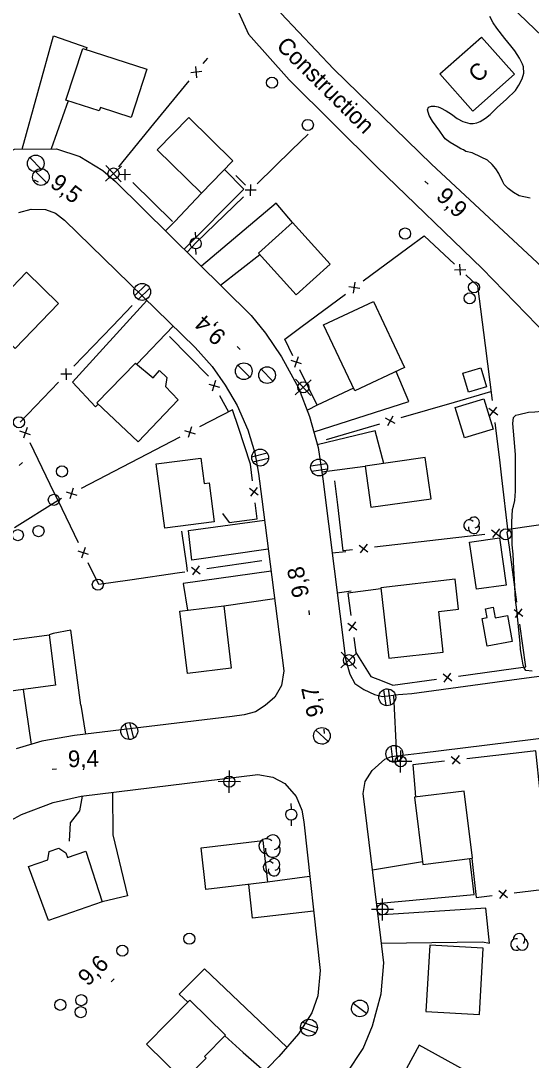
# Model space of a CAD drawing. Extents: x 381879 to 384696, y 5564785 to 5567594.
# Drawn here: x 383271.9 to 383363.8, y 5565601.7 to 5565788.8 of the extents above; entities that cross this region are included whole.
import ezdxf

# ---------------------------------------------------------------- set-up
doc = ezdxf.new("R2010")
doc.units = 0
for name, color, linetype in [('Niveau 1', 7, 'Continuous'), ('Niveau 19', 7, 'Continuous'), ('Niveau 21', 7, 'Continuous'), ('Niveau 3', 7, 'Continuous'), ('Niveau 31', 7, 'Continuous'), ('Niveau 36', 7, 'Continuous'), ('Niveau 37', 7, 'Continuous'), ('Niveau 41', 7, 'Continuous'), ('Niveau 44', 7, 'Continuous')]:
    doc.layers.add(name, color=color, linetype=linetype)

msp = doc.modelspace()

# ---------------------------------------------------------------- linework, layer by layer
at = {"layer": 'Niveau 1'}
for points in [[(383363.59, 5565756.86), (383361.64, 5565757.29), (383360.57, 5565757.89), (383359.63, 5565758.59), (383358.9, 5565759.33), (383358.68, 5565759.83), (383357.94, 5565761.3), (383357.43, 5565762.17), (383356.76, 5565762.92), (383355.91, 5565763.69), (383354.79, 5565764.27), (383353.13, 5565765.02), (383352.04, 5565765.29), (383351.6, 5565765.57), (383351.11, 5565765.74), (383350.61, 5565766.08), (383349.17, 5565766.92), (383348.32, 5565767.54), (383347.97, 5565767.98), (383347.33, 5565768.92), (383345.99, 5565770.73), (383345.42, 5565771.78), (383345.12, 5565772.78), (383345.29, 5565773.27), (383345.84, 5565773.45), (383346.44, 5565773.46), (383347.02, 5565773.34), (383347.48, 5565773.14), (383348.47, 5565772.62), (383349.44, 5565772), (383350.43, 5565771.23), (383351.48, 5565770.67), (383352.71, 5565770.32), (383353.33, 5565770.31), (383353.98, 5565770.42), (383354.6, 5565770.65), (383355.55, 5565771.25), (383356.37, 5565771.95), (383357.66, 5565773.18), (383359.32, 5565774.68), (383360.94, 5565776.25), (383361.58, 5565777.2), (383362.16, 5565778.35), (383362.45, 5565779.39), (383362.4, 5565780.51), (383362.23, 5565781.02), (383361.69, 5565782.05), (383360.82, 5565783.42), (383360.13, 5565784.32), (383359.05, 5565785.6), (383357.6, 5565787.47), (383356.95, 5565788.43), (383356.35, 5565789.59)], [(383360.98, 5565710.72), (383360.74, 5565713.52), (383360.45, 5565716.3), (383360.62, 5565717.41), (383361.01, 5565717.8), (383361.54, 5565717.94), (383363.32, 5565718.34), (383364.45, 5565718.4), (383365.68, 5565718.55), (383367.56, 5565718.87), (383369.37, 5565719.13), (383370.52, 5565719.14), (383371.63, 5565719.23), (383372.71, 5565719.42), (383373.81, 5565719.45), (383374.9, 5565719.24), (383375.95, 5565718.62)], [(383363.96, 5565671.74), (383362.85, 5565671.86), (383362.54, 5565672.29), (383362.36, 5565672.78), (383362.14, 5565673.9), (383361.87, 5565675.61), (383361.77, 5565676.74), (383361.51, 5565679.72), (383361.2, 5565682.76), (383360.96, 5565684.58), (383360.91, 5565685.64), (383360.8, 5565688.25), (383360.67, 5565690.17), (383360.53, 5565692.75), (383360.35, 5565694.43), (383360.34, 5565695.62), (383360.29, 5565698.52), (383360.43, 5565700.79), (383360.61, 5565701.4), (383360.81, 5565702.47), (383360.96, 5565704.14), (383360.96, 5565705.33), (383360.93, 5565708.19), (383360.95, 5565710.53), (383360.98, 5565710.72)]]:
    msp.add_lwpolyline(points, dxfattribs=at)
at = {"layer": 'Niveau 19'}
for points in [[(383272.12, 5565765.72), (383277.78, 5565786.1), (383283.8, 5565784.02), (383283.66, 5565783.63)], [(383280.42, 5565774.41), (383277.38, 5565765.74)], [(383308.55, 5565762.03), (383312.03, 5565758.51), (383301.29, 5565747.68)], [(383299.62, 5565752.66), (383304.4, 5565757.79)], [(383320.83, 5565752.49), (383317.89, 5565756), (383304.4, 5565744.61)], [(383299.62, 5565752.66), (383297.97, 5565750.96)], [(383303.47, 5565748.88), (383301.84, 5565747.14)], [(383307.82, 5565741.23), (383314.95, 5565746.7)], [(383285.83, 5565719.79), (383285.37, 5565719.31), (383281.18, 5565723.75), (383294.59, 5565738.42), (383294.61, 5565738.44)], [(383299.35, 5565733.82), (383292.76, 5565726.98)], [(383324.64, 5565714.79), (383324.73, 5565714.82), (383341.76, 5565720.29), (383339.49, 5565725.68)], [(383325.26, 5565719.63), (383323.5, 5565718.72), (383323.45, 5565718.7)], [(383337.24, 5565709.1), (383335.7, 5565715.01), (383325.27, 5565712.48)], [(383326.08, 5565707.59), (383333.87, 5565708.62)], [(383316.44, 5565693.68), (383302.69, 5565691.7), (383302.09, 5565697.02), (383315.77, 5565698.91)], [(383327.95, 5565692.99), (383330.44, 5565693.28)], [(383316.95, 5565689.71), (383301.14, 5565687.51), (383301.91, 5565682.67)], [(383331.36, 5565686.11), (383328.86, 5565685.75)], [(383308.43, 5565683.46), (383317.58, 5565684.81)], [(383282.73, 5565665.6), (383280.91, 5565679.09), (383277.7, 5565678.51), (383276.98, 5565678.23)], [(383272.34, 5565668.42), (383273.76, 5565658.54)], [(383282.73, 5565665.6), (383283.56, 5565660.37)], [(383280.65, 5565641.09), (383280.87, 5565644.42), (383282.53, 5565646.57), (383283.01, 5565649.21)], [(383288.42, 5565649.88), (383288.42, 5565649.8), (383288.44, 5565642.24), (383291.11, 5565631.26), (383286.54, 5565630.17)], [(383344.19, 5565637.4), (383335.21, 5565635.87)], [(383335.94, 5565629.86), (383353.51, 5565631.5), (383352.75, 5565637.96)], [(383323.92, 5565634.74), (383323.89, 5565634.74), (383316.32, 5565633.71)], [(383324.62, 5565628.53), (383313.62, 5565627.25), (383312.92, 5565633.32)], [(383355.03, 5565622.96), (383356.26, 5565622.76), (383355.62, 5565629.07), (383336.2, 5565627.78)], [(383336.8, 5565622.77), (383355.03, 5565622.96)], [(383319.81, 5565604), (383304.95, 5565618.1), (383300.38, 5565613.54), (383301.95, 5565612.12)], [(383308.64, 5565606.08), (383311.95, 5565603.09), (383315.79, 5565599.7)]]:
    msp.add_lwpolyline(points, dxfattribs=at)
at = {"layer": 'Niveau 21'}
for points in [[(383340.03, 5565839.61), (383323.72, 5565821.69), (383314.72, 5565812.08), (383308.82, 5565803.38), (383308.34, 5565796.45), (383312.87, 5565786.42), (383320.23, 5565778.18), (383336.03, 5565762.43), (383354.96, 5565744.23), (383378.72, 5565719.74), (383396.75, 5565701.57), (383402.38, 5565696.34)], [(383410.35, 5565703.77), (383396.72, 5565715.26), (383371.77, 5565738.86), (383345.81, 5565763), (383328.26, 5565780.1), (383318.72, 5565790.17), (383316.51, 5565795.66), (383316.17, 5565800.57), (383317.61, 5565803.6), (383321.37, 5565807.43), (383341.84, 5565826.74), (383347.6, 5565832.19), (383347.6, 5565832.19)], [(383165.2, 5565662.3), (383255.18, 5565754.08), (383259.47, 5565758.71), (383263.74, 5565762.5), (383270.79, 5565765.71), (383278.33, 5565765.75), (383282.52, 5565764.39), (383286.66, 5565761.84), (383288.94, 5565759.87), (383313.36, 5565735.76), (383315.98, 5565732.55), (383318.83, 5565728.32), (383321.91, 5565722.74), (383323.89, 5565717.55), (383325.41, 5565711.97), (383326.27, 5565706.34), (383330.34, 5565673.96), (383331.12, 5565671.16), (383332.04, 5565669.52), (383333.66, 5565668.42), (383335.55, 5565667.51), (383337.01, 5565667.18), (383339.08, 5565667.37)], [(383271.52, 5565754.32), (383273.79, 5565754.89), (383276.33, 5565754.84), (383278.17, 5565754.19), (383279.77, 5565752.88), (383303.28, 5565730), (383306.34, 5565726.55), (383308.7, 5565723.2), (383310.84, 5565719.55), (383312.78, 5565715.14), (383314.01, 5565711.05), (383314.66, 5565707.33), (383315.28, 5565702.69), (383319.26, 5565671.77), (383318.82, 5565669.13), (383317.65, 5565667.02), (383315.91, 5565665.54), (383314.17, 5565664.41), (383312.1, 5565663.86), (383309.96, 5565663.57), (383281.56, 5565660.13), (383275.66, 5565659.09), (383271.05, 5565657.75)], [(383339.61, 5565656.47), (383343.68, 5565656.98), (383388.48, 5565662.48), (383391.99, 5565663.35), (383396.16, 5565665.21), (383399.25, 5565667.19), (383403.25, 5565671.11), (383413, 5565680.41), (383416.17, 5565681.69), (383419.45, 5565680.99), (383421.64, 5565679.31), (383428.7, 5565687.33), (383426.92, 5565690.54), (383426.72, 5565693.02), (383427.78, 5565695.77), (383429.79, 5565697.9), (383459.04, 5565728.3), (383460.02, 5565728.69)], [(383402.38, 5565696.34), (383404.81, 5565693.32), (383405.33, 5565690.79), (383404.5, 5565688.15), (383392.17, 5565675.84), (383389.36, 5565674.25), (383385.14, 5565673.33), (383362.94, 5565670.46), (383342.29, 5565667.66), (383339.08, 5565667.37)], [(383339.61, 5565656.47), (383339.08, 5565667.37)], [(383279.7, 5565546.8), (383330.59, 5565599.35), (383333.54, 5565603.77), (383335.2, 5565607.85), (383336.77, 5565613.62), (383337.23, 5565619.22), (383336.69, 5565623.71), (383333.54, 5565649.66), (383333.88, 5565651.87), (383335.17, 5565653.84), (383337.46, 5565655.87), (383338.63, 5565656.35), (383339.61, 5565656.47)], [(383225.4, 5565600.6), (383260.79, 5565637.22), (383264.27, 5565640.61), (383268.01, 5565643.77), (383272.04, 5565645.91), (383277.7, 5565648.06), (383282.77, 5565649.18), (383314.56, 5565653.12), (383317.26, 5565652.66), (383319.46, 5565651.5), (383321.49, 5565649.13), (383322.5, 5565646.69), (383322.83, 5565644.58), (383325.81, 5565617.8), (383325.38, 5565613.29), (383324.28, 5565610.19), (383321.91, 5565606.43), (383318.36, 5565602.32), (383314.44, 5565598.32), (383271.8, 5565554.6)]]:
    msp.add_lwpolyline(points, dxfattribs=at)
at = {"layer": 'Niveau 3'}
for p, q in [((383274.32, 5565760.2), (383275, 5565759.79)), ((383344.65, 5565759.95), (383345.22, 5565759.38)), ((383311.4, 5565729.62), (383310.85, 5565730.19)), ((383271.61, 5565708.73), (383272.18, 5565709.3)), ((383323.9, 5565681.86), (383323.8, 5565682.65)), ((383326.59, 5565660.5), (383326.49, 5565661.29)), ((383277.54, 5565654.08), (383278.34, 5565654.14)), ((383288.15, 5565615.76), (383288.72, 5565616.33))]:
    msp.add_line(p, q, dxfattribs=at)
at = {"layer": 'Niveau 31'}
for points in [[(383347.36, 5565779.24), (383354.83, 5565785.88), (383360.76, 5565779.2), (383353.29, 5565772.56)], [(383283.07, 5565783.82), (383294.6, 5565780.08), (383291.78, 5565771.38), (383286.22, 5565773.18), (383286.02, 5565772.57), (383280.02, 5565774.54)], [(383302.12, 5565771.39), (383310.08, 5565763.58), (383304.4, 5565757.79), (383296.44, 5565765.6)], [(383320.83, 5565752.49), (383327.59, 5565745.01), (383321.47, 5565739.48), (383314.71, 5565746.96)], [(383278.71, 5565737.92), (383270.88, 5565729.83), (383265.1, 5565735.43), (383272.93, 5565743.52)], [(383335.39, 5565738.27), (383340.99, 5565726.39), (383332.01, 5565722.16), (383326.41, 5565734.04)], [(383300.23, 5565720.58), (383293.01, 5565712.99), (383285.57, 5565720.04), (383292.54, 5565727.17), (383295.72, 5565724.51), (383296.86, 5565725.86), (383298.2, 5565724.6), (383297.93, 5565722.95)], [(383355.71, 5565722.91), (383352.48, 5565721.96), (383351.48, 5565725.36), (383354.71, 5565726.31)], [(383351.76, 5565713.7), (383350.11, 5565719.16), (383355.28, 5565720.72), (383356.93, 5565715.26)], [(383297.8, 5565697.43), (383296.29, 5565709.02), (383304.29, 5565710.06), (383304.88, 5565705.51), (383305.79, 5565705.63), (383306.72, 5565698.61)], [(383344.72, 5565710.18), (383333.87, 5565708.62), (383334.93, 5565701.21), (383345.78, 5565702.76)], [(383358.09, 5565695.73), (383359.3, 5565687.22), (383353.91, 5565686.45), (383352.7, 5565694.96)], [(383336.7, 5565686.74), (383338.14, 5565674.04), (383347.96, 5565675.15), (383347.13, 5565682.46), (383350.7, 5565682.87), (383350.08, 5565688.28)], [(383301.89, 5565671.27), (383300.52, 5565682.5), (383308.43, 5565683.46), (383309.79, 5565672.23)], [(383359.52, 5565681.74), (383360.37, 5565677.04), (383355.86, 5565676.21), (383354.95, 5565681.19), (383355.83, 5565681.35), (383355.54, 5565682.96), (383356.96, 5565683.22), (383357.31, 5565681.33)], [(383265.72, 5565676.75), (383276.98, 5565678.23), (383278.16, 5565669.19), (383266.9, 5565667.71)], [(383353.24, 5565638.02), (383351.74, 5565650.14), (383342.75, 5565649.02), (383344.25, 5565636.9)], [(383316.32, 5565633.71), (383305.2, 5565632.43), (383304.34, 5565639.92), (383315.46, 5565641.2)], [(383286.54, 5565630.17), (383276.89, 5565626.82), (383273.31, 5565636.57), (383276.74, 5565637.73), (383277.02, 5565639.24), (383278.76, 5565639.87), (383280.02, 5565639.03), (383280.32, 5565638.18), (383283.6, 5565639.28)], [(383354.47, 5565609.9), (383355.15, 5565621.85), (383345.52, 5565622.39), (383344.84, 5565610.44)], [(383294.52, 5565604.57), (383302.33, 5565612.51), (383308.75, 5565606.19), (383304.98, 5565602.36), (383305.29, 5565602.06), (383301.24, 5565597.94)], [(383346.04, 5565589.44), (383351.78, 5565599.91), (383343.64, 5565604.37), (383337.9, 5565593.9)]]:
    msp.add_lwpolyline(points, close=True, dxfattribs=at)
at = {"layer": 'Niveau 36'}
for p, q in [((383275.65, 5565762.06), (383273.53, 5565764.18)), ((383287.12, 5565759.94), (383290.04, 5565762.66)), ((383289.94, 5565759.84), (383287.22, 5565762.76)), ((383276.59, 5565759.62), (383274.47, 5565761.74)), ((383303.31, 5565750.74), (383303.36, 5565749.74)), ((383303.46, 5565746.74), (383303.42, 5565747.74)), ((383294.44, 5565741.33), (383292.38, 5565739.29)), ((383293.04, 5565738.65), (383295.1, 5565740.69)), ((383313.11, 5565724.66), (383310.99, 5565726.78)), ((383317.3, 5565723.95), (383315.18, 5565726.07)), ((383321.28, 5565721.45), (383324.2, 5565724.17)), ((383324.1, 5565721.35), (383321.38, 5565724.27)), ((383316.27, 5565710.96), (383313.45, 5565710.27)), ((383313.69, 5565709.38), (383316.51, 5565710.07)), ((383326.96, 5565709.06), (383324.1, 5565708.6)), ((383324.26, 5565707.7), (383327.12, 5565708.16)), ((383329.5, 5565672.32), (383332.42, 5565675.04)), ((383332.32, 5565672.22), (383329.6, 5565675.14)), ((383337.21, 5565668.38), (383337.63, 5565665.51)), ((383338.53, 5565665.66), (383338.11, 5565668.53)), ((383290.62, 5565662.22), (383291.33, 5565659.41)), ((383292.22, 5565659.66), (383291.51, 5565662.47)), ((383327.23, 5565659.07), (383324.99, 5565661.07)), ((383338.51, 5565658.2), (383338.86, 5565655.32)), ((383339.77, 5565655.44), (383339.42, 5565658.32)), ((383340.28, 5565653.47), (383340.29, 5565657.45)), ((383342.28, 5565655.45), (383338.29, 5565655.47)), ((383309.43, 5565649.84), (383309.44, 5565653.82)), ((383311.43, 5565651.82), (383307.44, 5565651.84)), ((383320.51, 5565647.87), (383320.56, 5565646.87)), ((383320.66, 5565643.87), (383320.62, 5565644.87)), ((383337.02, 5565626.83), (383337.03, 5565630.81)), ((383339.02, 5565628.81), (383335.03, 5565628.83)), ((383334.12, 5565610.07), (383331.76, 5565611.91)), ((383322.27, 5565607.63), (383324.99, 5565606.62)), ((383325.29, 5565607.49), (383322.57, 5565608.5))]:
    msp.add_line(p, q, dxfattribs=at)
for centre, radius in [((383317.11, 5565777.66), 1), ((383323.57, 5565770.06), 1), ((383274.58, 5565763.12), 1.5), ((383275.52, 5565760.68), 1.5), ((383288.59, 5565761.31), 1), ((383341.08, 5565750.5), 1), ((383293.75, 5565739.99), 1.52), ((383353.48, 5565740.83), 1), ((383352.72, 5565738.85), 1), ((383312.04, 5565725.72), 1.5), ((383316.23, 5565725.01), 1.5), ((383322.75, 5565722.82), 1), ((383271.56, 5565716.53), 1), ((383279.31, 5565707.67), 1), ((383277.85, 5565702.56), 1), ((383271.36, 5565696.2), 1), ((383275.09, 5565696.92), 1), ((383359.19, 5565696.34), 1), ((383285.77, 5565687.3), 1), ((383330.97, 5565673.69), 1), ((383340.28, 5565655.47), 1), ((383309.43, 5565651.84), 1), ((383337.02, 5565628.83), 1), ((383302.24, 5565623.54), 1), ((383290.17, 5565621.39), 1), ((383282.78, 5565612.48), 1), ((383279, 5565611.64), 1), ((383282.69, 5565610.33), 1)]:
    msp.add_circle(centre, radius, dxfattribs=at)
for centre, major_axis, ratio in [((383303.39, 5565748.75), (-0.05, -0.999), 0.999983), ((383314.99, 5565710.17), (0.02, 1.52), 0.999983), ((383325.6, 5565708.38), (0.02, -1.52), 0.999984), ((383337.87, 5565667.01), (-0.06, -1.52), 0.999979), ((383291.42, 5565660.93), (-0.02, -1.52), 0.999982), ((383326.1, 5565660.07), (0.01, 1.5), 0.999982), ((383339.14, 5565656.83), (0.01, 1.52), 0.999982), ((383320.59, 5565645.88), (-0.05, -0.999), 0.999983), ((383332.93, 5565610.99), (-0.02, -1.5), 0.999984), ((383323.78, 5565607.55), (0.05, 1.52), 0.999983)]:
    msp.add_ellipse(centre, major_axis=major_axis, ratio=ratio, dxfattribs=at)
at = {"layer": 'Niveau 37'}
for p, q in [((383304.47, 5565779.65), (383302.48, 5565779.45)), ((383303.58, 5565778.55), (383303.38, 5565780.55)), ((383291.65, 5565761.12), (383289.65, 5565761.1)), ((383290.64, 5565762.11), (383290.65, 5565760.11)), ((383313.25, 5565757.31), (383313.28, 5565759.32)), ((383314.26, 5565758.3), (383312.26, 5565758.33)), ((383349.99, 5565743.97), (383351.99, 5565744.05)), ((383351.03, 5565743.01), (383350.95, 5565745.01)), ((383332.93, 5565740.63), (383330.95, 5565740.92)), ((383331.79, 5565739.78), (383332.09, 5565741.76)), ((383322.45, 5565727.03), (383320.55, 5565727.67)), ((383321.82, 5565728.3), (383321.18, 5565726.4)), ((383280.1, 5565724.18), (383280.06, 5565726.18)), ((383281.08, 5565725.2), (383279.08, 5565725.16)), ((383305.75, 5565723.4), (383307.67, 5565722.84)), ((383306.42, 5565722.16), (383306.99, 5565724.08)), ((383356.18, 5565719.08), (383357.77, 5565717.85)), ((383356.36, 5565717.67), (383357.59, 5565719.25)), ((383339.31, 5565716.32), (383337.56, 5565717.28)), ((383337.95, 5565715.92), (383338.91, 5565717.68)), ((383273.64, 5565714.28), (383271.75, 5565714.94)), ((383273.02, 5565715.56), (383272.36, 5565713.66)), ((383301.36, 5565715.06), (383303.27, 5565714.46)), ((383302.62, 5565715.71), (383302.01, 5565713.8)), ((383281.32, 5565704.65), (383280.72, 5565702.74)), ((383314.47, 5565704.78), (383313.23, 5565703.21)), ((383280.06, 5565704), (383281.97, 5565703.4)), ((383314.64, 5565703.38), (383313.07, 5565704.62)), ((383356.66, 5565697.16), (383358.23, 5565695.92)), ((383358.07, 5565697.32), (383356.83, 5565695.76)), ((383283.49, 5565693.96), (383282.84, 5565692.07)), ((383332.82, 5565694.41), (383334.39, 5565693.17)), ((383334.23, 5565694.57), (383332.98, 5565693.01)), ((383284.11, 5565692.69), (383282.22, 5565693.34)), ((383302.6, 5565690.45), (383304.21, 5565689.25)), ((383304, 5565690.65), (383302.81, 5565689.04)), ((383362.29, 5565681.56), (383360.69, 5565682.77)), ((383362.09, 5565682.96), (383360.88, 5565681.37)), ((383330.8, 5565680.38), (383332.4, 5565679.17)), ((383331, 5565678.98), (383332.21, 5565680.57)), ((383349.51, 5565669.94), (383347.91, 5565671.15)), ((383348.11, 5565669.75), (383349.31, 5565671.35)), ((383349.4, 5565656.36), (383350.97, 5565655.12)), ((383350.81, 5565656.52), (383349.56, 5565654.96)), ((383359.52, 5565630.93), (383357.95, 5565632.16)), ((383358.11, 5565630.76), (383359.35, 5565632.33))]:
    msp.add_line(p, q, dxfattribs=at)
for points in [[(383304.74, 5565781.1), (383305.54, 5565782.07)], [(383295.87, 5565770.27), (383302.21, 5565778)], [(383289.54, 5565762.53), (383295.87, 5565770.27)], [(383320.72, 5565765.57), (383323.64, 5565768.4)], [(383314.42, 5565759.48), (383320.72, 5565765.57)], [(383312.34, 5565759.23), (383310.63, 5565760.93)], [(383299.19, 5565752.68), (383292.07, 5565759.7)], [(383303.47, 5565748.88), (383312, 5565757.13)], [(383341.58, 5565747.92), (383344.49, 5565750.08)], [(383344.49, 5565750.08), (383349.98, 5565744.97)], [(383333.55, 5565741.96), (383341.58, 5565747.92)], [(383352.04, 5565743.05), (383354.14, 5565741.1)], [(383354.14, 5565741.1), (383355.48, 5565730.37)], [(383322.3, 5565733.62), (383330.33, 5565739.58)], [(383288.4, 5565733.82), (383291.97, 5565737.53)], [(383281.47, 5565726.62), (383288.4, 5565733.82)], [(383320.89, 5565728.47), (383319.41, 5565731.48), (383322.3, 5565733.62)], [(383298.67, 5565731.95), (383305.7, 5565724.84)], [(383355.48, 5565730.37), (383356.73, 5565720.45)], [(383331.78, 5565722.65), (383325.26, 5565719.63), (383322.11, 5565725.97)], [(383271.76, 5565716.53), (383278.69, 5565723.74)], [(383349.96, 5565720.15), (383356.52, 5565722.06)], [(383307.66, 5565721.36), (383309.28, 5565718.38)], [(383340.35, 5565717.36), (383349.96, 5565720.15)], [(383311.07, 5565715.61), (383310.02, 5565718.76), (383304.09, 5565715.68)], [(383326.91, 5565713.45), (383336.51, 5565716.24)], [(383357.22, 5565716.48), (383358.13, 5565709.23), (383358.45, 5565706.55)], [(383313.62, 5565705.99), (383313.27, 5565708.97), (383311.07, 5565715.61)], [(383277.93, 5565703.81), (383273.56, 5565712.81)], [(383300.54, 5565713.84), (383291.67, 5565709.23)], [(383291.67, 5565709.23), (383282.79, 5565704.62)], [(383358.45, 5565706.55), (383359.6, 5565696.79), (383359.47, 5565696.78), (383359.46, 5565696.77), (383359.44, 5565696.77), (383359.43, 5565696.77)], [(383328.95, 5565701.64), (383328.41, 5565706.01)], [(383279.24, 5565702.78), (383278.75, 5565702.52), (383278.6, 5565702.43), (383270.74, 5565697.52)], [(383282.29, 5565694.81), (383278.6, 5565702.43), (383277.93, 5565703.81)], [(383308.22, 5565700.11), (383309.41, 5565698.46), (383314.42, 5565699.12), (383314.08, 5565702.01)], [(383331.62, 5565693.56), (383329.96, 5565693.37), (383328.95, 5565701.64)], [(383301.92, 5565689.63), (383301.76, 5565690.72), (383300.88, 5565696.92)], [(383355.46, 5565696.31), (383345.53, 5565695.17)], [(383359.85, 5565694.05), (383359.48, 5565696.73), (383359.47, 5565696.78)], [(383345.53, 5565695.17), (383335.59, 5565694.02)], [(383361.21, 5565684.15), (383359.85, 5565694.05)], [(383315.28, 5565691.59), (383305.39, 5565690.14)], [(383291.53, 5565688.12), (383285.93, 5565687.31), (383284.04, 5565691.21)], [(383301.43, 5565689.56), (383300.48, 5565689.42), (383291.53, 5565688.12)], [(383336.72, 5565686.52), (383330.79, 5565685.74), (383331.33, 5565681.76)], [(383360.6, 5565672.19), (383362.82, 5565672.5), (383361.76, 5565680.18)], [(383331.87, 5565677.79), (383332.24, 5565675.09), (383334.91, 5565670.78), (383336.95, 5565669.96)], [(383350.69, 5565670.82), (383360.6, 5565672.19)], [(383336.95, 5565669.96), (383338.88, 5565669.19), (383346.73, 5565670.28)], [(383362.11, 5565657.1), (383352.17, 5565655.96)], [(383365.39, 5565649.94), (383364.61, 5565657.38), (383362.11, 5565657.1)], [(383348.2, 5565655.51), (383342.46, 5565654.86), (383342.83, 5565650.65)], [(383342.83, 5565650.65), (383342.97, 5565649.05)], [(383353.08, 5565638), (383353.85, 5565630.96), (383356.75, 5565631.31)], [(383360.72, 5565631.78), (383367.2, 5565632.56), (383366.84, 5565636.01)]]:
    msp.add_lwpolyline(points, dxfattribs=at)
at = {"layer": 'Niveau 41'}
for points in [[(383393.84, 5565759.18), (383335, 5565815.57)], [(383359.67, 5565697.28), (383394.13, 5565702.24)]]:
    msp.add_lwpolyline(points, dxfattribs=at)
at = {"layer": 'Niveau 44'}
for centre, radius, start, end in [((383353.49, 5565698.46), 0.989, 282.2692, 149.7262), ((383352.64, 5565697.96), 0.989, 44.1153, 269.8039), ((383353.49, 5565697.47), 0.989, 166.9368, 29.6212), ((383316.11, 5565640.22), 1.34, 44.1153, 269.8039), ((383317.26, 5565640.89), 1.34, 282.2692, 149.7262), ((383317.26, 5565639.54), 1.34, 166.9368, 29.6212), ((383316.59, 5565636.39), 1.04, 44.1153, 269.8039), ((383317.48, 5565636.92), 1.04, 282.2692, 149.7262), ((383317.48, 5565635.87), 1.04, 166.9368, 29.6212)]:
    msp.add_arc(centre, radius, start, end, dxfattribs=at)
for centre, start_param, end_param in [((383361.62, 5565623.43), 6.029753, 9.968762), ((383361.13, 5565622.51), 1.89021, 5.776785), ((383362.18, 5565622.55), 3.903138, 7.873013)]:
    msp.add_ellipse(centre, major_axis=(0.911, -0.513), ratio=0.999989, start_param=start_param, end_param=end_param, dxfattribs=at)

# ---------------------------------------------------------------- texts
at = {"layer": 'Niveau 21'}
msp.add_text('Construction', height=3, rotation=315.2577, dxfattribs=at).set_placement((383317.73, 5565784.09))
at = {"layer": 'Niveau 3'}
for s, rotation, p in [('9,5  ', 322.8177, (383276.97, 5565759.1)), ('9,9', 316.2518, (383346.48, 5565756.95)), ('9,4  ', 137.2389, (383309.05, 5565732.33)), ('9,8  ', 101.6505, (383323.84, 5565685.31)), ('9,7  ', 102.4818, (383326.48, 5565663.84)), ('9,4  ', 1.1661, (383280.4, 5565654.42)), ('9,6', 44.7717, (383283.98, 5565614.85))]:
    msp.add_text(s, height=3, rotation=rotation, dxfattribs=at).set_placement(p)
at = {"layer": 'Niveau 31'}
msp.add_text('C', height=3, rotation=44.7717, dxfattribs=at).set_placement((383354.26, 5565777.48))

doc.saveas('drawing.dxf')
